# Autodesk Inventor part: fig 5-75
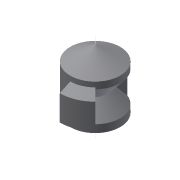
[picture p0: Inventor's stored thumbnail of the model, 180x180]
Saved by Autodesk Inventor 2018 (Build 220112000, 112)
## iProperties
Created: 2004-05
Part Number: fig 5-75
Document SubType Name: Modeling
Designer: CADCIM Technologies
Manufacturer: Standard
Standards Organization: Custom
Density: 1 g/cm^3
Material: Generic
Appearance: Default
Author: CADCIM Technologies
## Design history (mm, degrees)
sketch "Sketch1"
  geometry: L1 (0, -21.51)-(0, 21.51); L2 (0, 21.51)-(-14.639, 13.059); L3 (-14.639, 13.059)-(-14.639, -13.059); L4 (-14.639, -13.059)-(0, -21.51); 2 further points
  constraints: 8 end point, 1 coincident, 1 equal length, 1 midpoint, 1 parallel, 1 vertical, 1 other
  dimensions: "d3" = 120 deg angle of L4 L3
revolve "Revolution1" sketch "Sketch1" stored, may be unused: angle "d0" = 90 deg
workaxis "Work Axis1"
sketch "Sketch2"
  geometry: L1 (-15.658, 10.423)-(-7.144, 0); L2 (-7.144, 0)-(-15.658, -9.738); L3 (-15.658, -9.738)-(-15.658, 10.423); L4 (0, -25.812)-(0, 34.416) reference
  constraints: 6 end point, 1 vertical
revolve "Revolution2" sketch "Sketch2" stored, may be unused: angle "d4" = 140 deg
sketch "Sketch3"
  geometry: L1 (-14.955, 9.983)-(-20.736, 7.191); L2 (-20.736, 7.191)-(-20.736, -7.686); L3 (-20.736, -7.686)-(-15, -10.57); L4 (0, -25.812)-(0, 34.416) reference
  constraints: 6 end point, 1 equal length, 1 vertical
revolve "Revolution4" sketch "Sketch3" stored, may be unused: angle "d9" = 45 deg
body "Solid1"
other parameters: "d11" = 45 deg
